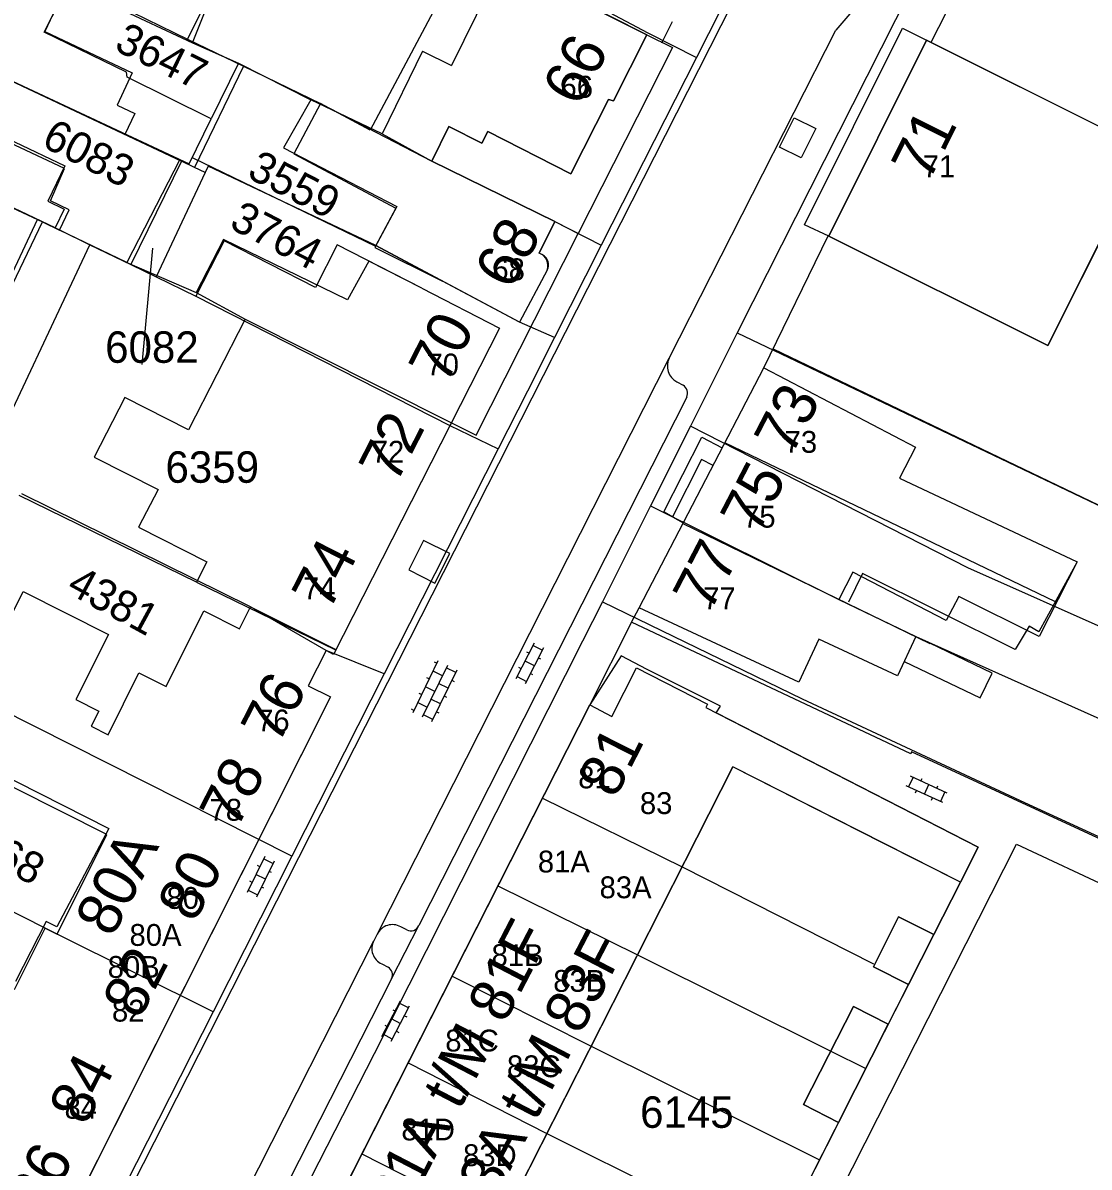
# Model space of a CAD drawing. Extents: x 148816 to 151297, y 399515 to 402500.
# Drawn here: x 150364.7 to 150425.7, y 399681.9 to 399747.3 of the extents above; entities that cross this region are included whole.
import ezdxf

# ---------------------------------------------------------------- set-up
doc = ezdxf.new("R2010")
doc.units = 0
for name, color, linetype in [('B01 Hoofdgebouw  [D] Norm', 7, 'Continuous'), ('B01 Hoofdgebouw  [T] Norm', 7, 'Continuous'), ('B01 hoofgebouw', 7, 'Continuous'), ('B02 Bijgebouw  [D] Norm', 7, 'Continuous'), ('B07 Tussenmuur  [D] Norm', 7, 'Continuous'), ('G01 perceelsgrens', 7, 'Continuous'), ('S02 Open verharding  Norm', 7, 'Continuous'), ('T04 Haag heg  [D] Gem', 7, 'Continuous'), ('V00 Kant verharding algemeen  [T] Norm', 7, 'Continuous'), ('Z01 perceelnummer', 7, 'Continuous'), ('Z02 huisnummer', 7, 'Continuous'), ('Z02 Huisnummer  [Tekst] Norm', 7, 'Continuous')]:
    doc.layers.add(name, color=color, linetype=linetype)

msp = doc.modelspace()

# ---------------------------------------------------------------- linework, layer by layer
at = {"layer": 'B01 Hoofdgebouw  [D] Norm'}
msp.add_line((150387.593, 399745.718), (150389.251, 399744.905), dxfattribs=at)
for points in [[(150392.067, 399750.633), (150389.251, 399744.905)], [(150359.32, 399746.24), (150374.222, 399739.274), (150375.495, 399741.84), (150370.671, 399744.234), (150370.646, 399744.513), (150365.923, 399746.805), (150366.84, 399748.609), (150364.327, 399750)], [(150366.348, 399750), (150374.408, 399746.188), (150375.916, 399750)], [(150345.37, 399716.89), (150348.687, 399715.327), (150349.731, 399717.41), (150352.575, 399716.035), (150353.033, 399716.771), (150356.232, 399715.218), (150358.371, 399719.614), (150355.274, 399721.218), (150355.706, 399722.031), (150354.082, 399722.922), (150355.126, 399725.005), (150352.51, 399726.203), (150355.592, 399732.707), (150362.625, 399729.294), (150365.834, 399735.951), (150366.799, 399735.468), (150367.359, 399736.636), (150366.293, 399737.146), (150367.083, 399739.001), (150361.09, 399741.802), (150362.083, 399743.835), (150358.89, 399745.33)], [(150387.593, 399745.718), (150385.276, 399740.992), (150381.188, 399742.928), (150379.635, 399740.184), (150386.109, 399736.823), (150384.862, 399734.485), (150388.725, 399732.56)], [(150387.55, 399732.15), (150384.504, 399733.71), (150383.283, 399731.487), (150376.199, 399734.951), (150374.62, 399731.902), (150377.438, 399730.374), (150374.179, 399724.048), (150370.548, 399725.906), (150368.791, 399722.476), (150372.447, 399720.643), (150371.327, 399718.483), (150375.237, 399716.497), (150374.651, 399715.328), (150364.495, 399720.294)], [(150415.156, 399710.793), (150419.51, 399708.704), (150420.198, 399710.126), (150416.636, 399711.842)], [(150361.708, 399705.249), (150369.63, 399701.225), (150366.651, 399695.61), (150366.042, 399695.916), (150364.285, 399692.486)]]:
    msp.add_lwpolyline(points, dxfattribs=at)
at = {"layer": 'B01 Hoofdgebouw  [T] Norm'}
for p, q in [((150400.42, 399746.65), (150395.97, 399748.91)), ((150398.51, 399742.87), (150400.42, 399746.65)), ((150410.85, 399735.13), (150416.44, 399746.34)), ((150416.44, 399746.34), (150428.99, 399740.08)), ((150396.08, 399738.7), (150398.24, 399742.96)), ((150398.24, 399742.96), (150398.51, 399742.87)), ((150388.12, 399739.43), (150389.09, 399741.41)), ((150389.09, 399741.41), (150390.98, 399740.45)), ((150390.98, 399740.45), (150391.32, 399741.12)), ((150391.32, 399741.12), (150396.08, 399738.7)), ((150428.99, 399740.08), (150423.39, 399728.87)), ((150395.16, 399735.97), (150388.12, 399739.43)), ((150394.27, 399734.16), (150395.16, 399735.97)), ((150423.39, 399728.87), (150410.85, 399735.13)), ((150394.46, 399734.059), (150394.27, 399734.16)), ((150394.725, 399733.19), (150393.14, 399730.21)), ((150387.55, 399732.15), (150392, 399729.87)), ((150393.14, 399730.21), (150388.725, 399732.56)), ((150392, 399729.87), (150389.16, 399724.31)), ((150399.98, 399713.87), (150407.12, 399727.59)), ((150407.12, 399727.59), (150415.81, 399723.06)), ((150389.16, 399724.31), (150382.48, 399711.2)), ((150415.81, 399723.06), (150414.89, 399721.29)), ((150414.89, 399721.29), (150425.07, 399716.5)), ((150409.12, 399709.6), (150399.98, 399713.87)), ((150410.27, 399712.07), (150409.12, 399709.6)), ((150414.77, 399709.97), (150410.27, 399712.07)), ((150415.83, 399712.23), (150414.77, 399709.97)), ((150382.07, 399711.43), (150381.03, 399709.39)), ((150382.48, 399711.2), (150382.07, 399711.43)), ((150398.42, 399707.65), (150399.84, 399710.43)), ((150399.84, 399710.43), (150403.9, 399708.35)), ((150381.03, 399709.39), (150382.32, 399708.77)), ((150382.32, 399708.77), (150373.77, 399691.78)), ((150378.9, 399672.33), (150397.16, 399708.31)), ((150397.16, 399708.31), (150398.42, 399707.65)), ((150403.9, 399708.35), (150403.8, 399708.16)), ((150403.8, 399708.16), (150419.39, 399700.17)), ((150386.844, 399668.292), (150405.353, 399704.761)), ((150418.38, 399698.16), (150405.353, 399704.761)), ((150419.39, 399700.17), (150418.38, 399698.16)), ((150413.4, 399693.32), (150414.84, 399696.17)), ((150414.84, 399696.17), (150416.85, 399695.16)), ((150416.85, 399695.16), (150415.41, 399692.31)), ((150415.41, 399692.31), (150413.4, 399693.32)), ((150373.77, 399691.78), (150365.63, 399675.61)), ((150409.4, 399685.43), (150412.25, 399691.05)), ((150412.25, 399691.05), (150414.25, 399690.03)), ((150414.25, 399690.03), (150411.4, 399684.41)), ((150411.4, 399684.41), (150409.4, 399685.43))]:
    msp.add_line(p, q, dxfattribs=at)
msp.add_lwpolyline([(150425.07, 399716.5), (150422.868, 399712.487), (150422.306, 399712.813), (150421.505, 399711.482), (150412.775, 399715.825), (150411.977, 399714.19)], dxfattribs=at)
msp.add_arc((150394.158, 399733.491), 0.642, 332.03777, 62.00086, dxfattribs=at)
at = {"layer": 'B01 hoofgebouw'}
for points in [[(150390.239, 399751.82), (150384.585, 399741.206), (150381.749, 399742.717), (150380.219, 399739.845), (150386.054, 399736.736), (150384.912, 399734.591), (150388.726, 399732.56)], [(150361.69, 399751.26), (150366.886, 399748.812), (150365.958, 399746.847), (150370.972, 399744.481), (150370.1, 399742.634), (150371.109, 399742.157), (150370.541, 399740.952), (150359.32, 399746.24)], [(150395.97, 399748.91), (150400.42, 399746.65), (150398.51, 399742.87), (150398.24, 399742.96), (150396.08, 399738.7), (150391.32, 399741.12), (150390.98, 399740.45), (150389.09, 399741.41), (150388.12, 399739.43), (150395.16, 399735.97), (150394.27, 399734.16)], [(150416.44, 399746.34), (150410.85, 399735.13), (150423.39, 399728.87), (150428.99, 399740.08), (150416.44, 399746.34)], [(150358.89, 399745.33), (150362.197, 399743.757), (150361.318, 399741.909), (150367.109, 399739.156), (150366.144, 399737.127), (150367.077, 399736.683), (150366.564, 399735.604), (150352.012, 399742.519)], [(150352.45, 399726.387), (150355.45, 399732.739), (150362.408, 399729.452), (150365.543, 399736.089)], [(150387.55, 399732.15), (150382.706, 399734.632), (150381.462, 399732.193), (150376.223, 399734.865), (150374.613, 399731.708), (150389.156, 399724.292)], [(150394.726, 399733.189), (150393.139, 399730.21), (150388.726, 399732.56)], [(150387.55, 399732.15), (150392, 399729.87), (150382.48, 399711.2), (150382.07, 399711.43), (150381.03, 399709.39), (150382.32, 399708.77), (150365.63, 399675.61), (150357.74, 399679.58), (150357.8, 399679.69), (150354.23, 399681.37), (150352.86, 399678.63), (150362.47, 399673.81), (150358.88, 399666.65), (150354.41, 399668.89)], [(150415.83, 399712.23), (150414.77, 399709.97), (150410.27, 399712.07), (150409.12, 399709.6), (150399.98, 399713.87), (150407.12, 399727.59), (150415.81, 399723.06), (150414.89, 399721.29), (150425.07, 399716.5), (150422.88, 399712.23)], [(150422.88, 399712.23), (150418.286, 399714.519), (150417.563, 399713.13), (150412.221, 399715.91), (150411.408, 399714.348), (150415.83, 399712.23)], [(150361.762, 399708.899), (150364.717, 399714.793), (150369.608, 399712.341), (150367.739, 399708.613), (150369.055, 399707.953), (150368.62, 399707.085), (150369.582, 399706.602), (150371.353, 399710.135), (150372.903, 399709.359), (150375.071, 399713.683), (150377.11, 399712.661), (150377.741, 399713.92), (150382.62, 399711.474)], [(150387.46, 399656.76), (150385.9, 399653.68), (150384.99, 399653.42), (150372.51, 399659.67), (150377.55, 399669.64), (150378.75, 399669.03), (150380.1, 399671.72), (150378.9, 399672.33), (150397.16, 399708.31), (150398.42, 399707.65), (150399.84, 399710.43), (150403.9, 399708.35), (150403.8, 399708.16), (150419.39, 399700.17), (150418.38, 399698.16), (150413.92, 399700.42)], [(150364.227, 399692.012), (150365.992, 399695.532), (150366.661, 399695.196), (150369.514, 399700.887), (150361.648, 399704.832)], [(150413.92, 399700.42), (150405.353, 399704.761), (150386.876, 399668.355), (150394.756, 399664.407), (150394.51, 399663.988), (150391.082, 399665.567), (150389.681, 399663.027), (150388.539, 399663.562), (150385.721, 399658.35), (150386.876, 399657.726), (150387.46, 399656.76)], [(150415.41, 399692.31), (150416.85, 399695.16), (150414.84, 399696.17), (150413.4, 399693.32), (150415.41, 399692.31)], [(150411.4, 399684.41), (150414.25, 399690.03), (150412.25, 399691.05), (150409.4, 399685.43), (150411.4, 399684.41)]]:
    msp.add_lwpolyline(points, dxfattribs=at)
msp.add_arc((150394.002, 399733.442), 0.766, 340.74156, 69.56972, dxfattribs=at)
at = {"layer": 'B02 Bijgebouw  [D] Norm'}
for p, q in [((150374.651, 399715.328), (150382.608, 399711.451)), ((150410.955, 399688.495), (150412.964, 399687.495))]:
    msp.add_line(p, q, dxfattribs=at)
at = {"layer": 'B07 Tussenmuur  [D] Norm'}
for p, q in [((150351.954, 399742.398), (150365.834, 399735.951)), ((150351.954, 399742.398), (150365.834, 399735.951)), ((150377.438, 399730.374), (150389.235, 399724.458)), ((150377.438, 399730.374), (150389.235, 399724.458)), ((150423.83, 399714.208), (150404.89, 399723.306)), ((150423.83, 399714.208), (150404.89, 399723.306)), ((150402.488, 399718.688), (150416.629, 399711.827)), ((150402.488, 399718.688), (150416.629, 399711.827)), ((150394.45, 399702.97), (150402.449, 399699.04)), ((150394.45, 399702.97), (150402.449, 399699.04)), ((150391.905, 399697.956), (150399.892, 399694.001)), ((150391.905, 399697.956), (150399.892, 399694.001)), ((150389.28, 399692.782), (150397.24, 399688.775)), ((150389.28, 399692.782), (150397.24, 399688.775)), ((150386.761, 399687.819), (150394.703, 399683.777)), ((150386.761, 399687.819), (150394.703, 399683.777)), ((150384.12, 399682.615), (150392.064, 399678.577)), ((150384.12, 399682.615), (150392.064, 399678.577))]:
    msp.add_line(p, q, dxfattribs=at)
msp.add_lwpolyline([(150385.276, 399740.992), (150388.12, 399739.43)], dxfattribs=at)
msp.add_lwpolyline([(150385.276, 399740.992), (150388.12, 399739.43)], dxfattribs=at)
at = {"layer": 'G01 perceelsgrens'}
for points in [[(150420.372, 399758.806), (150406.495, 399731.381), (150405.604, 399729.605)], [(150383.199, 399755.636), (150390.407, 399752.135), (150400.48, 399746.769), (150403.267, 399745.362)], [(150357.59, 399754.25), (150371.006, 399747.928), (150374.129, 399746.413)], [(150406.709, 399752.157), (150403.267, 399745.362)], [(150376.724, 399751.677), (150374.129, 399746.413)], [(150354.8, 399748.37), (150373.794, 399739.415)], [(150374.129, 399746.413), (150377.334, 399744.859)], [(150403.267, 399745.362), (150397.821, 399734.613)], [(150377.334, 399744.859), (150374.536, 399739.064)], [(150377.334, 399744.859), (150381.749, 399742.717), (150388.12, 399739.43), (150395.16, 399735.97), (150397.821, 399734.613)], [(150352.012, 399742.519), (150366.834, 399735.473), (150368.544, 399734.645)], [(150373.794, 399739.415), (150370.878, 399733.516)], [(150374.536, 399739.064), (150373.794, 399739.415)], [(150375.145, 399738.776), (150372.329, 399732.813)], [(150375.145, 399738.776), (150374.536, 399739.064)], [(150395.144, 399729.328), (150393.139, 399730.21), (150384.912, 399734.591), (150375.313, 399739.131), (150375.145, 399738.776)], [(150362.363, 399721.516), (150368.544, 399734.645)], [(150368.544, 399734.645), (150370.878, 399733.516)], [(150397.821, 399734.613), (150395.144, 399729.328)], [(150370.878, 399733.516), (150372.329, 399732.813)], [(150372.329, 399732.813), (150374.613, 399731.708), (150389.156, 399724.292), (150391.919, 399722.963)], [(150405.604, 399729.605), (150402.927, 399724.266)], [(150405.604, 399729.605), (150429.07, 399718.4), (150453.23, 399706.71)], [(150395.144, 399729.328), (150393.587, 399726.254), (150391.919, 399722.963)], [(150402.927, 399724.266), (150400.637, 399719.7)], [(150450.909, 399701.942), (150435.79, 399708.599), (150418.798, 399716.153), (150402.927, 399724.266)], [(150391.919, 399722.963), (150385.395, 399710.087)], [(150385.395, 399710.087), (150382.07, 399711.43), (150377.741, 399713.92), (150364.645, 399720.389)], [(150400.637, 399719.7), (150397.885, 399714.212)], [(150400.637, 399719.7), (150411.408, 399714.348), (150415.83, 399712.23), (150448.74, 399697.486)], [(150397.885, 399714.212), (150396.75, 399711.949), (150384.809, 399688.338), (150377.141, 399673.334)], [(150397.885, 399714.212), (150409.325, 399708.664), (150422.051, 399702.72), (150448.296, 399690.663)], [(150406.016, 399668.847), (150404.16, 399669.818), (150406.26, 399674.27), (150416.85, 399695.16), (150418.38, 399698.16), (150419.39, 399700.17), (150404.401, 399707.852), (150404.649, 399708.241), (150400.448, 399710.341), (150398.95, 399711.109), (150397.16, 399708.31), (150378.9, 399672.33)], [(150385.395, 399710.087), (150380.11, 399699.657)], [(150380.11, 399699.657), (150363.3, 399708.128), (150361.762, 399708.899), (150360.903, 399709.321)], [(150375.591, 399690.738), (150366.661, 399695.196), (150356.232, 399700.424)], [(150380.11, 399699.657), (150375.591, 399690.738)], [(150375.591, 399690.738), (150367.46, 399674.691)]]:
    msp.add_lwpolyline(points, dxfattribs=at)
at = {"layer": 'S02 Open verharding  Norm'}
for p, q in [((150393.98, 399711.839), (150392.93, 399709.793)), ((150394.514, 399711.565), (150393.464, 399709.519)), ((150393.683, 399711.261), (150393.55, 399711.329)), ((150393.911, 399711.706), (150394.445, 399711.432)), ((150388.471, 399710.827), (150387.028, 399707.859)), ((150389.01, 399710.565), (150387.568, 399707.597)), ((150388.405, 399710.692), (150388.27, 399710.758)), ((150393.989, 399710.542), (150393.455, 399710.816)), ((150394.351, 399710.919), (150394.217, 399710.987)), ((150387.968, 399709.793), (150387.833, 399709.859)), ((150389.55, 399710.303), (150388.107, 399707.335)), ((150388.726, 399709.98), (150388.186, 399710.243)), ((150389.484, 399710.168), (150388.945, 399710.43)), ((150392.999, 399709.926), (150393.533, 399709.652)), ((150393.227, 399710.371), (150393.093, 399710.439)), ((150393.894, 399710.029), (150393.761, 399710.097)), ((150388.289, 399709.081), (150387.749, 399709.343)), ((150389.047, 399709.268), (150388.508, 399709.531)), ((150389.266, 399709.718), (150389.401, 399709.653)), ((150387.531, 399708.894), (150387.396, 399708.959)), ((150388.61, 399708.369), (150388.07, 399708.631)), ((150388.829, 399708.819), (150388.964, 399708.753)), ((150387.094, 399707.994), (150386.959, 399708.06)), ((150387.312, 399708.444), (150387.852, 399708.182)), ((150388.392, 399707.919), (150388.526, 399707.854)), ((150388.173, 399707.47), (150387.633, 399707.732)), ((150415.664, 399704.164), (150415.413, 399703.619)), ((150417.617, 399703.265), (150415.528, 399704.226)), ((150416.118, 399703.955), (150416.181, 399704.091)), ((150417.366, 399702.72), (150415.277, 399703.681)), ((150415.805, 399703.273), (150415.867, 399703.41)), ((150416.322, 399703.2), (150416.572, 399703.746)), ((150417.027, 399703.536), (150417.089, 399703.673)), ((150417.481, 399703.327), (150417.23, 399702.782)), ((150416.713, 399702.855), (150416.776, 399702.991)), ((150378.561, 399699.628), (150377.54, 399697.567)), ((150379.098, 399699.361), (150378.077, 399697.3)), ((150378.494, 399699.493), (150379.032, 399699.227)), ((150378.272, 399699.045), (150378.138, 399699.112)), ((150378.944, 399698.712), (150378.81, 399698.779)), ((150377.828, 399698.149), (150377.694, 399698.216)), ((150378.588, 399698.331), (150378.05, 399698.597)), ((150377.606, 399697.701), (150378.144, 399697.435)), ((150378.5, 399697.816), (150378.366, 399697.883)), ((150385.255, 399689.331), (150386.317, 399691.372)), ((150385.787, 399689.054), (150386.849, 399691.095)), ((150385.884, 399690.864), (150386.017, 399690.795)), ((150386.78, 399690.962), (150386.248, 399691.239)), ((150385.786, 399690.352), (150386.318, 399690.074)), ((150386.549, 399690.518), (150386.682, 399690.449)), ((150385.422, 399689.977), (150385.555, 399689.908)), ((150386.087, 399689.631), (150386.22, 399689.562)), ((150385.856, 399689.187), (150385.324, 399689.464))]:
    msp.add_line(p, q, dxfattribs=at)
at = {"layer": 'T04 Haag heg  [D] Gem'}
for p, q in [((150402.448, 399699.037), (150413.395, 399693.483)), ((150399.892, 399694.001), (150410.955, 399688.496)), ((150397.24, 399688.776), (150410.317, 399682.273)), ((150394.704, 399683.779), (150405.771, 399678.27))]:
    msp.add_line(p, q, dxfattribs=at)
for points in [[(150374.408, 399746.188), (150377.049, 399745.041)], [(150377.049, 399745.041), (150375.495, 399741.84)], [(150377.049, 399745.041), (150381.188, 399742.928)], [(150373.692, 399739.524), (150370.659, 399733.634)], [(150374.399, 399739.631), (150384.902, 399734.56)], [(150370.659, 399733.634), (150366.799, 399735.468)], [(150370.659, 399733.634), (150374.62, 399731.902)], [(150402.511, 399718.734), (150401.393, 399719.353), (150403.573, 399723.637), (150404.744, 399723.025)]]:
    msp.add_lwpolyline(points, dxfattribs=at)
at = {"layer": 'V00 Kant verharding algemeen  [T] Norm'}
for p, q in [((150418.605, 399750), (150416.69, 399746.21)), ((150401.29, 399746.2), (150401.9, 399747.41)), ((150400.42, 399746.65), (150401.89, 399745.92)), ((150401.698, 399728.149), (150411.252, 399746.919)), ((150409.45, 399735.78), (150415.07, 399747.03)), ((150415.07, 399747.03), (150416.44, 399746.34)), ((150401.89, 399745.92), (150396.49, 399735.29)), ((150395.16, 399735.97), (150396.491, 399735.291)), ((150410.85, 399735.13), (150409.45, 399735.78)), ((150407.12, 399727.59), (150410.798, 399735.155)), ((150407.65, 399728.68), (150429.07, 399718.4)), ((150385.02, 399695.241), (150401.698, 399728.149)), ((150399.55, 399713.04), (150399.98, 399713.87)), ((150415.53, 399705.51), (150399.55, 399713.04)), ((150415.58, 399705.62), (150415.53, 399705.51)), ((150429.52, 399699.17), (150415.58, 399705.62)), ((150406.47, 399670.52), (150421.59, 399700.34)), ((150421.59, 399700.34), (150433.76, 399694.65)), ((150418.38, 399698.16), (150416.85, 399695.16)), ((150385.81, 399692.631), (150387.369, 399695.677)), ((150367.634, 399660.993), (150384.806, 399694.812)), ((150415.41, 399692.31), (150414.25, 399690.03)), ((150411.4, 399684.41), (150409.1, 399679.87))]:
    msp.add_line(p, q, dxfattribs=at)
for points in [[(150420.749, 399761.617), (150416.395, 399752.95), (150411.252, 399746.919)], [(150368.424, 399675.79), (150406.595, 399750.97), (150412.724, 399758.313), (150413.32, 399759.488)], [(150410.095, 399741.285), (150409.252, 399739.609), (150408.022, 399740.228), (150408.865, 399741.904), (150410.095, 399741.285)], [(150389.235, 399724.458), (150390.647, 399723.75), (150396.49, 399735.29)], [(150402.139, 399726.788), (150402.502, 399726.613)], [(150402.718, 399725.92), (150387.369, 399695.677)], [(150404.215, 399722.007), (150403.546, 399722.343), (150401.887, 399719.063), (150402.509, 399718.73)], [(150388.296, 399715.283), (150389.142, 399716.976), (150387.65, 399717.723), (150386.803, 399716.03), (150388.296, 399715.283)], [(150399.55, 399713.04), (150397.16, 399708.31)], [(150386.691, 399695.428), (150386.339, 399695.607)], [(150384.993, 399695.189), (150384.806, 399694.812)], [(150385.247, 399693.481), (150385.612, 399693.304)], [(150385.81, 399692.631), (150369.975, 399661.479)]]:
    msp.add_lwpolyline(points, dxfattribs=at)
for centre, radius, start, end in [((150402.649, 399727.705), 1.05, 154.9959, 240.91149), ((150402.157, 399726.125), 0.597, 339.89875, 54.72454), ((150385.863, 399694.765), 0.968, 60.50902, 153.99531), ((150386.918, 399695.857), 0.486, 242.11774, 338.21444), ((150385.641, 399694.35), 0.955, 151.06781, 245.59534), ((150385.344, 399692.859), 0.519, 333.88387, 58.90442)]:
    msp.add_arc(centre, radius, start, end, dxfattribs=at)
at = {"layer": 'Z01 perceelnummer'}
msp.add_lwpolyline([(150371.529, 399727.785), (150372.155, 399734.455)], dxfattribs=at)

# ---------------------------------------------------------------- texts
for s, rotation, p in [('3647', 333.81948, (150369.865, 399745.818)), ('6083', 332.74313, (150365.702, 399740.32)), ('3559', 332.66592, (150377.466, 399738.528)), ('3764', 332.40733, (150376.451, 399735.634)), ('4381', 331.41689, (150367.126, 399714.778)), ('4268', 331.41689, (150360.596, 399700.498))]:
    msp.add_text(s, height=1.8, rotation=rotation, dxfattribs=at).set_placement(p)
for s, p in [('6082', (150369.417, 399727.885)), ('6359', (150372.87, 399721.02)), ('6145', (150400.041, 399684.104))]:
    msp.add_text(s, height=1.8, dxfattribs=at).set_placement(p)
at = {"layer": 'Z02 huisnummer'}
for s, rotation, p in [('66', 63.12746, (150396.593, 399742.478)), ('71', 63.51182, (150416.563, 399738.183)), ('68', 61.89718, (150392.671, 399731.983)), ('70', 62.94832, (150388.917, 399726.584)), ('73', 62.53777, (150408.691, 399722.486)), ('72', 62.94832, (150386.066, 399720.878)), ('75', 62.53777, (150406.753, 399718.004)), ('77', 62.53777, (150404.033, 399713.535)), ('74', 62.94832, (150382.232, 399713.605)), ('76', 62.94832, (150379.316, 399705.965)), ('81', 63.12746, (150398.607, 399702.875)), ('78', 62.94832, (150376.949, 399701.126)), ('80A', 62.94832, (150369.827, 399694.933)), ('80', 62.94832, (150374.533, 399695.776)), ('81A t/M 81F', 62.53777, (150386.529, 399678.954)), ('83A t/M 83F', 62.53777, (150390.874, 399678.315)), ('82', 62.94832, (150371.386, 399690.238)), ('84', 62.94832, (150368.31, 399684.15)), ('86', 62.94832, (150365.953, 399679.04))]:
    msp.add_text(s, height=2.5, rotation=rotation, dxfattribs=at).set_placement(p)
at = {"layer": 'Z02 Huisnummer  [Tekst] Norm'}
for s, p in [('66', (150395.485, 399743.06)), ('71', (150416.22, 399738.505)), ('68', (150391.585, 399732.61)), ('70', (150387.81, 399727.16)), ('73', (150408.315, 399722.735)), ('72', (150384.678, 399722.17)), ('75', (150405.937, 399718.451)), ('74', (150380.746, 399714.357)), ('77', (150403.65, 399713.78)), ('76', (150378.115, 399706.791)), ('81', (150396.498, 399703.535)), ('83', (150400.031, 399702.062)), ('78', (150375.392, 399701.681)), ('81A', (150394.188, 399698.716)), ('83A', (150397.721, 399697.243)), ('80', (150372.928, 399696.634)), ('80A', (150370.813, 399694.517)), ('81B', (150391.538, 399693.36)), ('80B', (150369.564, 399692.685)), ('83B', (150395.071, 399691.887)), ('82', (150369.807, 399690.184)), ('81C', (150388.888, 399688.473)), ('83C', (150392.421, 399687)), ('84', (150367.092, 399684.625)), ('81D', (150386.374, 399683.386)), ('83D', (150389.907, 399681.913))]:
    msp.add_text(s, height=1.25, dxfattribs=at).set_placement(p)

doc.saveas('drawing.dxf')
